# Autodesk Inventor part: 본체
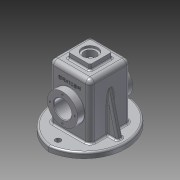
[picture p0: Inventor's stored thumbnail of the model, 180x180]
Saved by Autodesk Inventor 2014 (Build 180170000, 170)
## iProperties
Created: 2017-07
Part Number: 본체
Material: 알루미늄 6061
Document SubType Name: Modeling
Designer: user
Mass: 925.928 g
Surface Area: 965.8 cm^2
Volume: 341.671 cm^3
Density: 2.71 g/cm^3
Appearance: 알루미늄 - 평지
Author: user
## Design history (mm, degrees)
sketch "스케치1"
  geometry: L1 (-37, -37)-(37, -37); L2 (37, -37)-(37, 37); L3 (37, 37)-(-37, 37); L4 (-37, 37)-(-37, -37); L5 (-37, -37)-(37, 37); L6 (37, -37)-(-37, 37); 1 further point
  constraints: 12 end point, 2 midpoint, 2 parallel, 1 horizontal, 1 perpendicular
  dimensions: "d0" = 74 distance of L1.start L1.end; "d1" = 74 distance of L1.end L2.end
extrude "돌출1" new body sketch "스케치1" stored distance "d2" = 90; taper "d3" = 0 deg
node "작업 평면1"
sketch "스케치2"
  geometry: L1 (-75, -65)-(75, -65); L2 (75, -65)-(75, 65); L3 (75, 65)-(-75, 65); L4 (-75, 65)-(-75, -65); L5 (-75, -65)-(75, 65); L6 (75, -65)-(-75, 65); 1 further point
  constraints: 12 end point, 2 midpoint, 2 parallel, 1 horizontal, 1 perpendicular
  dimensions: "d5" = 150 distance of L2.end L3.end; "d6" = 130 distance of L3.end L1.start
extrude "돌출2" join sketch "스케치2" stored distance "d7" = 90; taper "d8" = 0 deg
sketch "스케치5"
  geometry: L1 (0, 0)-(0, 130) reference; L2 (150, 0)-(0, 0) reference; L3 (150, 130)-(150, 0) reference; L4 (0, 130)-(150, 130) reference; L5 (0, 130)-(0, 0) reference; L6 (0, 65)-(150, 65); A1 r 75.769 centre (75, 54.231) between (150, 65) and (0, 65); A2 r 75.769 centre (75, 75.769) between (0, 65) and (150, 65); 1 further point
  constraints: 4 point on circle, 2 centre point, 2 end point, 2 midpoint, 1 perpendicular, 1 symmetric about line, 1 other
  dimensions: "d29" = 130 distance of L1.start L1.end (derived)
extrude "돌출5" cut sketch "스케치5" stored distance "d15" = 13; taper "d16" = 0 deg
sketch "스케치7"
  geometry: 1 further point
sketch "스케치8"
  geometry: L1 (-37, -37)-(37, -37); L2 (37, -37)-(37, 37); L3 (37, 37)-(-37, 37); L4 (-37, 37)-(-37, -37); L5 (-37, -37)-(37, 37); L6 (37, -37)-(-37, 37); 1 further point
  constraints: 12 end point, 2 midpoint, 2 parallel, 1 horizontal, 1 perpendicular
extrude "돌출6" join sketch "스케치8" distance "d20" = 10; taper "d21" = 0 deg
sketch "스케치12"
  geometry: 1 further point
sketch "스케치13"
  geometry: C1 r 27.5 at (45, 37); 1 further point
  constraints: 1 centre point, 1 coincident
  dimensions: "d30" = 55 diameter of C1
extrude "돌출9" join sketch "스케치13" distance "d31" = 13; taper "d32" = 0 deg
sketch "스케치14"
  geometry: C1 r 27.5 at (-45, 37); 1 further point
  constraints: 1 centre point, 1 coincident
  dimensions: "d33" = 55 diameter of C1
extrude "돌출10" join sketch "스케치14" distance "d34" = 13; taper "d35" = 0 deg
sketch "스케치15"
  geometry: L1 (65, -45)-(-65, -45) reference; L2 (-65, -45)-(-55, -45); L3 (0, -45)-(-65, -45) reference; L4 (-65, -45)-(-65, 69.043); L5 (-55, -45)-(-32.5, 45.243); L6 (-55, -45)-(-32.5, -45); L7 (-32.5, -45)-(-55, -45); L8 (-55, -45)-(-32.5, -45); L9 (-37, 55)-(-37, -45) reference; L10 (37, 55)-(-37, 55) reference; L11 (37, -45)-(37, 55) reference; L12 (-37, -45)-(37, -45) reference; L13 (-32.5, 45.243)-(-32.5, -45); L14 (-37, 55)-(-37, -45) reference; L15 (-32.5, -45)-(-55, -45); C1 r 27.5 at (0, 0) reference; 1 further point
  constraints: 16 end point, 4 collinear, 1 midpoint, 1 parallel, 1 perpendicular, 1 point on line
  dimensions: "d36" = 10 distance of L1.end L2.end; "d37" = 14 deg angle of L5 L4
  node "투영된 루프1"
sketch "스케치16"
  geometry: 1 further point
extrude "돌출11" join sketch "스케치15" stored distance "d38" = 10; taper "d39" = 0 deg
sketch "스케치17"
  geometry: L1 (-20, -20)-(20, -20); L2 (20, -20)-(20, 20); L3 (20, 20)-(-20, 20); L4 (-20, 20)-(-20, -20); L5 (-20, -20)-(20, 20); L6 (20, -20)-(-20, 20); 1 further point
  constraints: 12 end point, 2 midpoint, 2 parallel, 1 horizontal, 1 perpendicular
  dimensions: "d40" = 40 distance of L3.end L2.end; "d41" = 40 distance of L2.end L1.end
extrude "돌출12" join sketch "스케치17" distance "d42" = 10; taper "d43" = 0 deg
sketch "스케치18"
  geometry: L1 (-50, 27.5)-(-50, -27.5) reference; L2 (-50, 0)-(50, 0); L3 (50, -27.5)-(50, 27.5) reference; L4 (-50, 0)-(-50, 16); L5 (-50, 16)-(-25, 16); L6 (-37, -45)-(-37, 55) reference; L7 (-25, 16)-(-25, 20.5); L8 (-25, 20.5)-(-32, 27.5); L9 (-32, 27.5)-(-32, 50); L10 (-32, 50)-(32, 50); L11 (32, 50)-(32, 27.5); L12 (32, 27.5)-(25, 20.5); L13 (25, 20.5)-(25, 16); L14 (25, 16)-(50, 16); L15 (37, 55)-(-37, 55) reference; L16 (0, 50)-(0, -55); L17 (-75, -55)-(75, -55) reference; L18 (-32, -27.5)-(-32, -50); L19 (-25, -20.5)-(-32, -27.5); L20 (32, -50)-(32, -27.5); L21 (32, -27.5)-(25, -20.5); L22 (25, -20.5)-(25, -16); L23 (25, -16)-(50, -16); L24 (-50, -16)-(-25, -16); L25 (-50, -27.5)-(-50, 27.5); L26 (-25, -20.5)-(-25, -16); L27 (32, -50)-(32, -55); L28 (-32, -50)-(-32, -55); L29 (-25, 16)-(-25, -16); L30 (25, 16)-(25, -16); L31 (-32, -55)-(32, -55); L32 (50, 16)-(50, -16); 1 further point
  constraints: 54 end point, 12 symmetric about line, 7 parallel, 7 perpendicular, 5 point on line, 4 midpoint, 1 collinear
  dimensions: "d44" = 16 distance of L2.start L4.end; "d45" = 5 distance between parallel lines of L10 L15; "d46" = 7 distance between parallel lines of L11 L13; "d47" = 7 distance between parallel lines of L9 L7; "d48" = 55 diameter of L8.end L2; "d49" = 55 diameter of L11.end L2; "d50" = 32 diameter of L14 L2; "d51" = 135 deg angle of L9 L8; "d52" = 135 deg angle of L11 L12 (derived); "d53" = 64 distance of L9.end L10.end; "d54" = 25 distance of L4.end L5.end
extrude "돌출13" cut sketch "스케치18" stored distance "d55" = 64; taper "d56" = 0 deg
sketch "스케치19"
  geometry: C1 r 27.5 at (0, 0) reference; C2 r 16 at (0, 0)
  constraints: 1 centre point, 1 coincident
  dimensions: "d57" = 32 diameter of C2
extrude "돌출14" cut sketch "스케치19" stored distance "d58" = 64; taper "d59" = 0 deg
sketch "스케치20"
  geometry: C1 r 14 at (0, 0); 1 further point
  constraints: 1 centre point, 1 coincident
  dimensions: "d60" = 28 diameter of C1
extrude "돌출15" cut sketch "스케치20" distance "d61" = 4; taper "d62" = 0 deg
sketch "스케치21"
  geometry: C1 r 14 at (0, 0) reference; C2 r 10.5 at (0, 0)
  constraints: 1 centre point, 1 coincident
  dimensions: "d63" = 21 diameter of C2
extrude "돌출16" cut sketch "스케치21" stored distance "d64" = 4; taper "d65" = 0 deg
sketch "스케치22"
  geometry: L1 (-5, 44.231)-(5, 44.231) reference; L2 (0, -10.769)-(0, 32.025); C1 r 5 at (58, -10.769); C2 r 5 at (-58, -10.769); A1 r 75.769 centre (0, -21.538) between (75, -10.769) and (-75, -10.769) reference; 1 further point
  constraints: 2 centre point, 2 end point, 1 perpendicular, 1 point on circle, 1 symmetric about line, 1 other
  dimensions: "d66" = 10 diameter of C1; "d68" = 58 distance of L2.start C1.centre
extrude "돌출17" cut sketch "스케치22" stored distance "d69" = 4; taper "d70" = 0 deg
sketch "스케치23" dims "d71" = 45
  geometry: C1 r 27.5 at (0, 0) reference; 2 further points
  constraints: 1 coincident, 1 horizontal alignment, 2 other
hole "구멍1" sketch "스케치23" at (-22.5, 0) diameter "d72" = 3.242; stored, may be unused: countersink angle "d76" = 90 deg, drill point angle "d78" = 118 deg; dims "d73" = 8, "d74" = 4, "d75" = 2, "d77" = 10
fillet "모깎기1" dims "d82" = 8
fillet "모깎기2" dims "d83" = 8
fillet "모깎기3" dims "d84" = 3
fillet "모깎기4" dims "d85" = 3
fillet "모깎기5" dims "d86" = 3
fillet "모깎기6" dims "d87" = 3
fillet "모깎기7" dims "d88" = 3
fillet "모깎기8" dims "d89" = 3
fillet "모깎기9" dims "d90" = 3
fillet "모깎기10" dims "d91" = 3
fillet "모깎기11" dims "d92" = 3
chamfer "모따기1" distance "d93" = 1; stored, may be unused: second distance "d94" = 2, angle "d95" = 45 deg
chamfer "모따기2" distance "d96" = 1; stored, may be unused: second distance "d97" = 2, angle "d98" = 45 deg
fillet "모깎기12" dims "d99" = 0.5
node "작업 평면2"
sketch "스케치25"
  geometry: L1 (89, 66)-(0, 66) reference; L2 (-18, 12)-(-18, 46) reference; 2 further points
  constraints: 1 other
  dimensions: "d103" = 37 distance from line of L1 point (12, 29); "d104" = 30 distance from line of L2 point (12, 29)
feature "엠보싱1" sketch "스케치25" dims "d5" = 150, "d105" = 0.5, "d106" = 0
node "솔리드1"
mirror "대칭1"
pattern_circular "원형 패턴1" dims angle "d80" = 360 deg
mirror "대칭2"
mirror "대칭3"
other parameters: "d4" = -55, "d102" = 5
